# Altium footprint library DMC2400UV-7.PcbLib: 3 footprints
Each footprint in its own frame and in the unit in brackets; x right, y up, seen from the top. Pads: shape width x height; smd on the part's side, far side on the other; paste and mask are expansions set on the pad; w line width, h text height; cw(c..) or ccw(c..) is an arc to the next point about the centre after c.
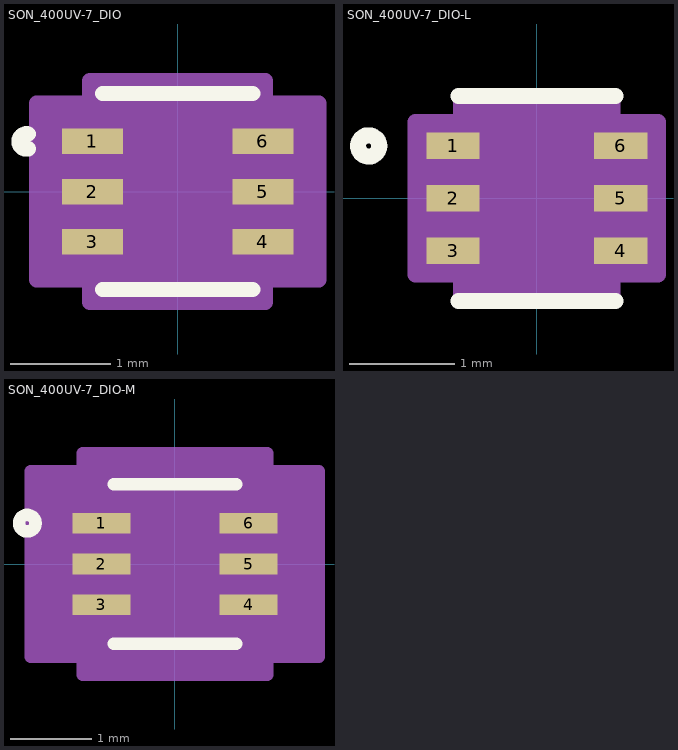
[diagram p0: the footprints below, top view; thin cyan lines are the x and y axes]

## SON_400UV-7_DIO [mil]
pads (6):
  rect 24x10 smd paste+0 mask+0: 1(-33.5,19.68) 2(-33.5,0) 3(-33.5,-19.68) 4(33.5,-19.68) 5(33.5,0) 6(33.5,19.68)
Top Overlay:
  lines w6: -58.6,16.78 cw(c-59.34,19.68) -58.6,22.59 ; -29.5,-38.5 29.5,-38.5 ; -29.5,38.5 29.5,38.5
  text ".Designator" at -137.5,-25 h50
Mechanical 13:
  circle w6: c-21.5,19.68 r0
  lines w1: -12,33.5 ccw(c0,33.5) 12,33.5 ; -24.5,-33.5 24.5,-33.5 24.5,33.5 -24.5,33.5 -24.5,-33.5
  text ".Designator" at -137.5,-25 h50
Mechanical 15:
  region: -34.5,-34.69 -55.5,-34.69 -55.5,34.69 -34.5,34.69 -34.5,43.5 34.5,43.5 34.5,34.69 55.5,34.69 55.5,-34.69 34.5,-34.69 34.5,-43.5 -34.5,-43.5
  lines w6: -55.5,-34.69 -55.5,34.69 -34.5,34.69 -34.5,43.5 34.5,43.5 34.5,34.69 55.5,34.69 55.5,-34.69 34.5,-34.69 34.5,-43.5 -34.5,-43.5 -34.5,-34.69 -55.5,-34.69
3D body "SON_400UV-7_DIO.step": height 24.09, standoff 0, extent -33.5,-33.5 33.5,33.5

## SON_400UV-7_DIO-L [mil]
pads (6):
  rect 20x10 smd paste+0 mask+0: 1(-31.5,19.68) 2(-31.5,0) 3(-31.5,-19.68) 4(31.5,-19.68) 5(31.5,0) 6(31.5,19.68)
Top Overlay:
  circle w6: c-63.19,19.68 r4
  lines w6: -29.5,-38.5 29.5,-38.5 ; -29.5,38.5 29.5,38.5
  text ".Designator" at -137.5,-25 h50
Mechanical 13:
  circle w1: c-21.5,19.68 r3
  lines w1: -12,33.5 ccw(c0,33.5) 12,33.5 ; -24.5,-33.5 24.5,-33.5 24.5,33.5 -24.5,33.5 -24.5,-33.5
  text ".Designator" at -137.5,-25 h50
Mechanical 15:
  region: -28.5,-28.68 -45.5,-28.68 -45.5,28.68 -28.5,28.68 -28.5,37.5 28.5,37.5 28.5,28.68 45.5,28.68 45.5,-28.68 28.5,-28.68 28.5,-37.5 -28.5,-37.5
  lines w6: -45.5,-28.68 -45.5,28.68 -28.5,28.68 -28.5,37.5 28.5,37.5 28.5,28.68 45.5,28.68 45.5,-28.68 28.5,-28.68 28.5,-37.5 -28.5,-37.5 -28.5,-28.68 -45.5,-28.68
3D body "SON_400UV-7_DIO.step": height 24.09, standoff 0, extent -33.5,-33.5 33.5,33.5

## SON_400UV-7_DIO-M [mil]
pads (6):
  rect 28x10 smd paste+0 mask+0: 1(-35.5,19.68) 2(-35.5,0) 3(-35.5,-19.68) 4(35.5,-19.68) 5(35.5,0) 6(35.5,19.68)
Top Overlay:
  circle w6: c-71.19,19.68 r4
  lines w6: -29.5,-38.5 29.5,-38.5 ; -29.5,38.5 29.5,38.5
  text ".Designator" at -137.5,-25 h50
Mechanical 13:
  circle w1: c-21.5,19.68 r3
  lines w1: -12,33.5 ccw(c0,33.5) 12,33.5 ; -24.5,-33.5 24.5,-33.5 24.5,33.5 -24.5,33.5 -24.5,-33.5
  text ".Designator" at -137.5,-25 h50
Mechanical 15:
  region: -44.5,-44.69 -69.5,-44.69 -69.5,44.69 -44.5,44.69 -44.5,53.5 44.5,53.5 44.5,44.69 69.5,44.69 69.5,-44.69 44.5,-44.69 44.5,-53.5 -44.5,-53.5
  lines w6: -69.5,-44.69 -69.5,44.69 -44.5,44.69 -44.5,53.5 44.5,53.5 44.5,44.69 69.5,44.69 69.5,-44.69 44.5,-44.69 44.5,-53.5 -44.5,-53.5 -44.5,-44.69 -69.5,-44.69
3D body "SON_400UV-7_DIO.step": height 24.09, standoff 0, extent -33.5,-33.5 33.5,33.5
